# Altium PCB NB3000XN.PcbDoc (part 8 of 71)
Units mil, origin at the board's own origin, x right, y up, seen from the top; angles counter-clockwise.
Board outline 9527.56 x 6929.77 mil, 6 copper layers (Top Layer, GND+SHIELD, MidLayer1, MidLayer2, P2 - 3V3+5V0, Bottom Layer), stack 62.375 mil thick; 832 components, 1027 nets, 4655 pads, 4981 vias.
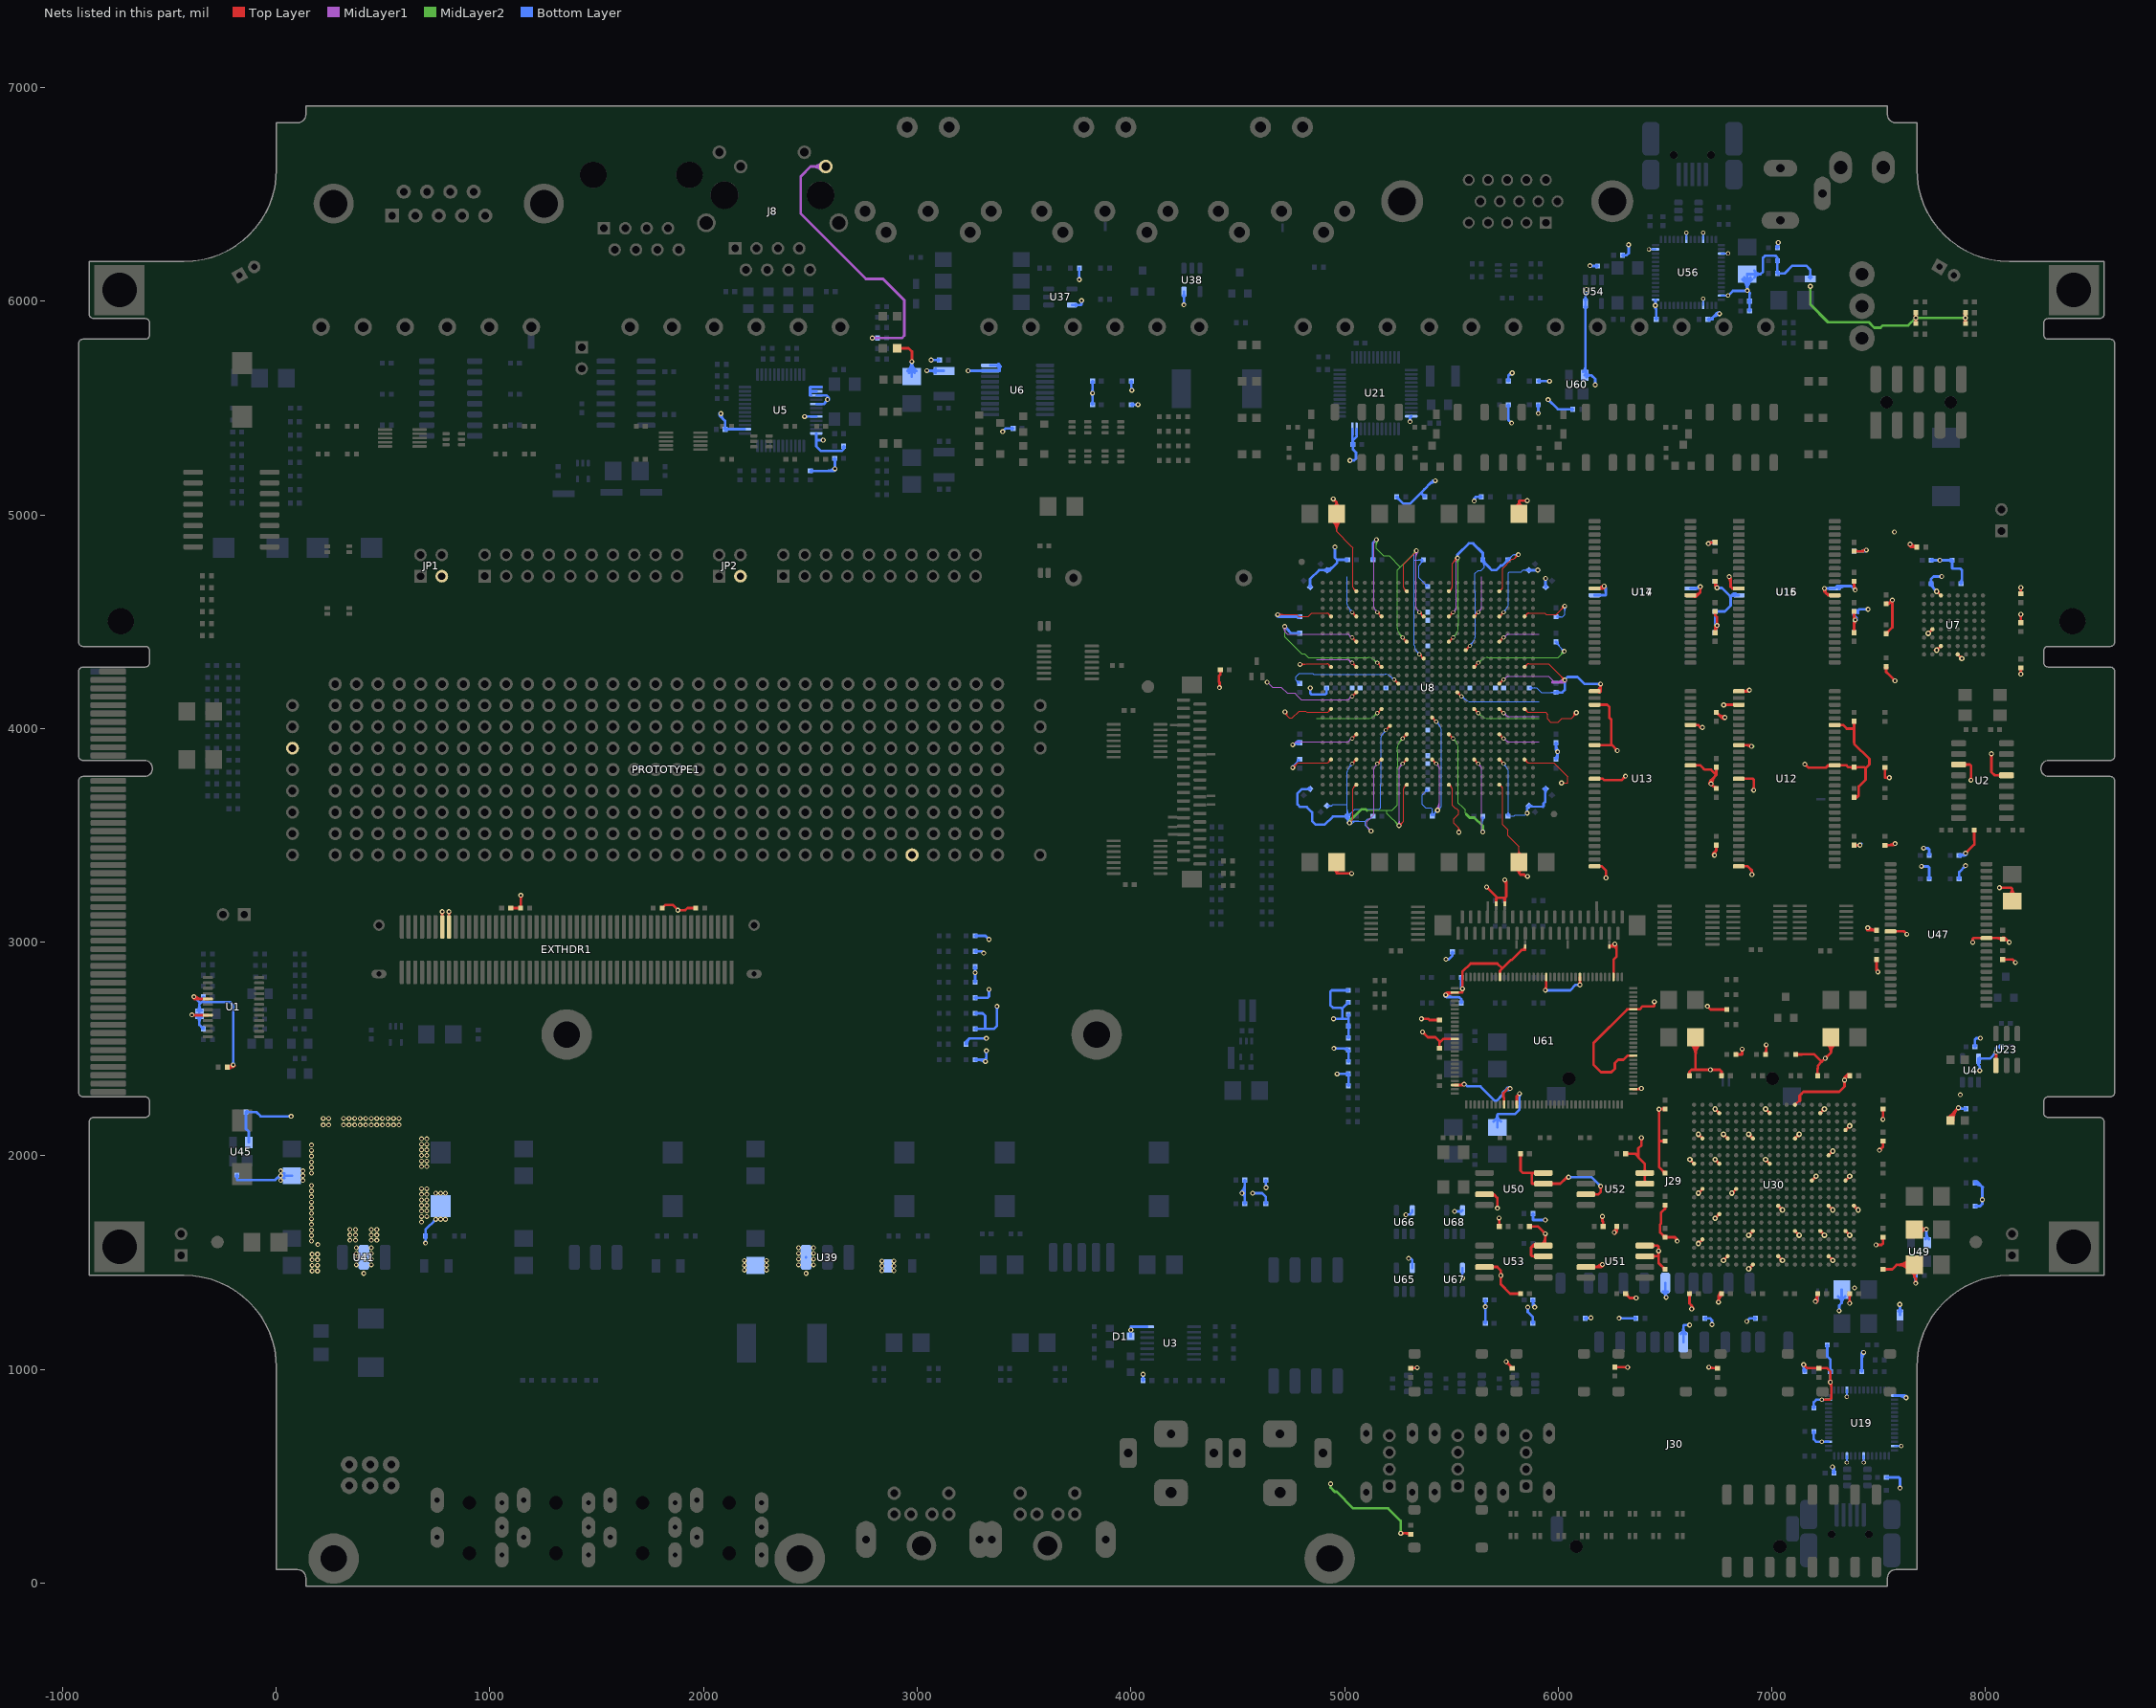
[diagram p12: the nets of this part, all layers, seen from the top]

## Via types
v1: diameter 23, hole 11.81, Top Layer to Bottom Layer, 3672 vias
v2: diameter 26, hole 11.81, Top Layer to Bottom Layer, 461 vias
v3: diameter 19, hole 11.81, Top Layer to Bottom Layer, tented both sides, 396 vias
v4: diameter 23.62, hole 11.81, Top Layer to Bottom Layer, 288 vias
v5: diameter 20, hole 11.81, Top Layer to Bottom Layer, 91 vias
v6: diameter 23, hole 11.81, Top Layer to Bottom Layer, tented both sides, 50 vias
v7: diameter 31, hole 11.81, Top Layer to Bottom Layer, 15 vias
v8: diameter 27.56, hole 11.81, Top Layer to Bottom Layer, tented both sides, 4 vias
v9: diameter 29, hole 11.81, Top Layer to Bottom Layer, 3 vias
v10: diameter 21, hole 11.81, Top Layer to Bottom Layer, 1 vias

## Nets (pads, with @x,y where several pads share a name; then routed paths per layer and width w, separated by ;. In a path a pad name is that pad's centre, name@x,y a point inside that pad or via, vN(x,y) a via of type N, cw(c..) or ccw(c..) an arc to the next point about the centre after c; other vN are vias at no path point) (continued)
3V3: (continued)
  Bottom Layer w4: v1@4757.52,3824.04 4758.52,3825.04 4758.7,3825.04 C322.1@4790,3856.34 ; v1@4757.52,3826.21 ccw(c4757.52,3831.87) 4761.53,3827.87 ; v1(4757.52,3924.04) v1@4758.52,3925.04 ; v1@4759.02,3816.71 cw(c4779.92,3816.71) 4765.14,3831.48 ; v1@4763.02,3816.71 cw(c4793.58,3816.71) 4771.97,3838.31 ; v1@4767.02,3816.71 cw(c4807.23,3816.71) C322.1@4778.8,3845.14 ; C322.1@4780.19,3856.34 cw(c4756.5,3856.34) 4773.25,3839.59 cw(c4790,3822.84) C322.1@4790,3846.53 ; C335.1@4780.19,4210.78 ccw(c4757.43,4211.05) 4773.53,4227.14 ; C323.1@4781.46,3928.28 ccw(c4773.19,3923.61) 4773.19,3933.11 ; C323.1@4781.46,3937.93 cw(c4773.19,3942.6) 4773.19,3933.11 ; C322.1@4784.19,3856.34 cw(c4770.16,3856.34) 4780.08,3846.42 cw(c4790,3836.5) C322.1@4790,3850.53 ; C335.1@4784.19,4210.74 ccw(c4770.71,4210.9) 4780.24,4220.43 ccw(c4789.77,4229.96) C335.1@4789.93,4216.48 ; C335.1@4789.89,4220.48 cw(c4789.62,4243.24) 4773.53,4227.14 ; C323.1@4790,3933.11 4773.19,3933.11 ; C335.1@4790,4210.67 4773.52,4227.15 ; C326.1@4917.56,3638.82 4940.19,3638.82 ; C326.1@4921.8,3634.85 cw(c4930.96,3626.27) 4930.96,3638.82 cw(c4930.96,3651.37) C326.1@4921.8,3642.79 ; C326.1@4924.72,3632.11 cw(c4940.19,3617.62) 4940.19,3638.82 ; C326.1@4924.72,3645.53 ccw(c4940.19,3660.01) 4940.19,3638.82 ; 4940.19,3639.04 4945.86,3644.71 5005,3644.71 ; 4948.52,3591.71 5000.42,3591.71 ; C331.1@5008.06,3596.94 ccw(c4998.8,3606.2) 5011.9,3606.2 ; 5008.57,3644.71 5005,3644.71 ; 5011.61,3644.71 5005,3644.71 ; C331.1@5011.9,3596.9 5011.9,3660 5011.9,3670 5011.9,3679.78 5011.9,3738.04 5011.9,3796.3 cw(c5035.67,3796.3) 5018.86,3813.11 5025.28,3820.84 ; 5011.9,3601.86 ccw(c5026.86,3601.86) C331.1@5016.28,3591.28 ; 5011.9,3611.51 ccw(c5036.51,3611.51) C331.1@5019.11,3594.11 ; 5011.9,3621.17 ccw(c5046.17,3621.17) C331.1@5021.94,3596.94 ; 5011.9,3648.22 5011.9,3655.26 ; 5011.9,4710 5011.9,4641.96 5011.9,4583.7 ccw(c5035.67,4583.7) 5018.86,4566.89 5025.28,4559.16 ; C331.1@5012.8,3580.44 cw(c5009.71,3566.97) v1@5023.52,3566.97 ; C331.1@5013.7,3584.34 cw(c5010.86,3572) 5023.52,3572 ; C331.1@5014.59,3588.24 cw(c5012.02,3577.02) 5023.52,3577.02 ; C331.1@5015,3595.81 ccw(c5015,3609.84) 5024.92,3599.92 ccw(c5034.84,3590) C331.1@5020.81,3590 ; C331.1@5015,3599.81 ccw(c5015,3623.5) 5031.75,3606.75 ccw(c5048.5,3590) C331.1@5024.81,3590 ; v1@5016.81,3565.09 ccw(c5000.59,3581.31) 5023.52,3581.31 ccw(c5046.46,3581.31) v1@5030.24,3565.09 ; v1@5019.64,3562.26 ccw(c5010.25,3571.65) 5023.52,3571.65 ccw(c5036.8,3571.65) v1@5027.41,3562.26 ; v1@5021.76,3560.14 cw(c5037.61,3544.29) 5037.61,3566.71 ; v1@5024.58,3557.31 cw(c5047.26,3534.64) 5047.26,3566.71 ; v1@5027.41,3554.49 cw(c5056.92,3524.98) 5056.92,3566.71 ; v3@5028.28,3834.37 cw(c5010.45,3831.22) 5025.28,3820.84 ; v3@5028.28,4545.63 ccw(c5010.45,4548.78) 5025.28,4559.16 ; v1@5030.24,3551.66 cw(c5066.58,3515.32) 5066.58,3566.71 ; v3@5036.97,3828.28 ccw(c5040.12,3810.45) 5025.28,3820.84 ; v3@5036.97,4551.72 cw(c5040.12,4569.55) 5025.28,4559.16 ; v1@5115.02,3520.71 ccw(c5092.09,3520.71) 5108.31,3536.93 ccw(c5124.52,3553.14) v1@5124.52,3530.21 ; v1@5119.02,3520.71 ccw(c5105.75,3520.71) 5115.14,3530.1 ccw(c5124.52,3539.49) v1@5124.52,3526.21 ; v1(5124.52,3520.71) 5098.52,3546.71 5098.52,3566.71 ; C330.1@5133.11,3590 5119.82,3576.71 5108.52,3576.71 5098.52,3566.71 ; 5169.38,3655.26 5169.38,3660 ; v3@5185.76,3991.85 cw(c5167.93,3988.7) 5182.76,3978.32 ; v3@5194.45,3985.76 ccw(c5197.6,3967.93) 5182.76,3978.32 ; v3@5225.05,4228.72 ccw(c5207.01,4227.14) 5218.65,4241.01 ; v3@5231.87,4236.84 cw(c5230.29,4254.88) 5218.65,4241.01 ; v1(5336.67,4832.5) 5337.54,4833.37 5339.52,4833.37 5326.77,4820.62 5326.77,4790 ; v3@5343.16,4348.13 ccw(c5325.12,4349.71) 5338.99,4361.35 ; 5350.34,4765.34 ccw(c5328,4787.67) C332.1@5359.54,4789.45 ; v3@5351.28,4354.95 cw(c5352.86,4372.99) 5338.99,4361.35 ; 5356.65,4771.65 ccw(c5339.97,4788.34) C332.1@5363.53,4789.67 ; 5362.26,4777.26 cw(c5369.33,4770.19) C332.1@5369.33,4780.19 ; C332.1@5362.39,4783.06 ccw(c5345.65,4766.31) 5345.65,4790 ccw(c5345.65,4813.69) C332.1@5362.39,4796.94 ; 5362.97,4777.97 ccw(c5351.93,4789.02) C332.1@5367.52,4789.9 ; C332.1@5365.22,4785.89 ccw(c5355.3,4775.97) 5355.3,4790 ccw(c5355.3,4804.03) C332.1@5365.22,4794.11 ; C317.1@5380.19,3715.59 cw(c5356.5,3715.59) 5373.25,3698.84 cw(c5390,3682.09) C317.1@5390,3705.78 ; C315.1@5380.19,4664.41 ccw(c5356.5,4664.41) 5373.25,4681.16 ccw(c5390,4697.91) C315.1@5390,4674.22 ; C317.1@5384.19,3715.59 cw(c5370.16,3715.59) 5380.08,3705.67 cw(c5390,3695.75) C317.1@5390,3709.78 ; C315.1@5384.19,4664.41 ccw(c5370.16,4664.41) 5380.08,4674.33 ccw(c5390,4684.25) C315.1@5390,4670.22 ; C317.1@5390,3715.59 5365,3690.59 5365,3670 5365,3660 5365,3645 5380,3630 5405,3630 5410.67,3624.33 C333.1@5410.67,3590 5410.67,3593.19 v1(5435.52,3618.04) 5453.23,3635.75 5453.23,3651.25 5453.23,3655.26 5453.23,3660 5453.23,3670 5453.23,3876.1 5453.23,3895.52 5453.23,3969.64 5453.23,3989.14 ccw(c5411.5,3989.14) 5441.01,4018.65 ; C313.1@5390,3873.07 C313.1@5390,3882.3 ; C315.1@5390,4664.41 5347.5,4706.91 5347.5,4710 5347.5,4720 5347.5,4762.5 5369.33,4784.33 C332.1@5369.33,4790 5326.77,4790 ; C333.1@5403.73,3596.94 ccw(c5386.98,3613.69) 5410.67,3613.69 ccw(c5434.36,3613.69) C333.1@5417.61,3596.94 ; C333.1@5406.56,3594.11 ccw(c5396.64,3604.03) 5410.67,3604.03 ccw(c5424.7,3604.03) C333.1@5414.78,3594.11 ; C333.1@5410.67,3599.81 ccw(c5410.67,3615.8) 5421.98,3604.5 ; C333.1@5416.48,3590 cw(c5438.2,3590) 5422.84,3605.36 ; C333.1@5420.48,3590 cw(c5451.86,3590) v1@5429.67,3612.19 ; v1@5426.02,3618.04 cw(c5403.09,3618.04) 5419.31,3601.82 cw(c5435.52,3585.61) v1@5435.52,3608.54 ; v3@5428.72,4025.05 cw(c5427.14,4007.01) 5441.01,4018.65 ; v1@5430.02,3618.04 cw(c5416.75,3618.04) 5426.13,3608.65 cw(c5435.52,3599.26) v1@5435.52,3612.54 ; v1@5435.52,3623.54 ccw(c5435.52,3636.82) 5444.91,3627.43 ccw(c5454.3,3618.04) v1@5441.02,3618.04 ; v1@5435.52,3627.54 ccw(c5435.52,3650.48) 5451.74,3634.26 ccw(c5467.96,3618.04) v1@5445.02,3618.04 ; v3@5436.84,4031.87 ccw(c5454.88,4030.29) 5441.01,4018.65 ; v3@5548.13,4143.16 cw(c5549.71,4125.12) 5561.35,4138.99 ; v3@5554.95,4151.28 ccw(c5572.99,4152.86) 5561.35,4138.99 ; v3@5585.55,4394.24 ccw(c5582.4,4412.07) 5597.24,4401.68 ; v3@5594.24,4388.15 cw(c5612.07,4391.3) 5597.24,4401.68 ; 5595.52,4866.71 5646.89,4815.34 ; C328.1@5639.95,3583.06 cw(c5623.2,3566.31) 5646.89,3566.31 cw(c5670.57,3566.32) C328.1@5653.83,3583.06 ; v1@5640.47,3522.76 ccw(c5624.98,3538.25) 5646.89,3538.25 ; C291.1@5640.8,4782.31 cw(c5619.23,4755.04) 5654,4755.04 ; C328.1@5642.78,3585.89 cw(c5632.86,3575.97) 5646.89,3575.97 cw(c5660.92,3575.97) C328.1@5651,3585.89 ; C291.1@5643.29,4785.44 cw(c5625.77,4763.3) 5654,4763.3 ; v1@5643.3,3519.93 ccw(c5634.64,3528.59) 5646.89,3528.59 ; C291.1@5645.77,4788.58 cw(c5632.31,4771.57) 5654,4771.57 ; 5646.89,3530.04 ccw(c5661.19,3530.04) v1@5651.08,3519.93 ; 5646.89,3539.7 ccw(c5670.85,3539.7) v1@5653.91,3522.76 ; C328.1@5646.89,3590 5646.89,3516.34 v1(5647.19,3516.04) ; C291.1@5646.89,4790 5654,4782.89 5654,4777.9 5654,4755.77 5638.23,4740 5624.8,4740 5610.62,4725.82 5610.62,4720 5610.62,4710 ; C291.1@5648.25,4791.72 cw(c5638.85,4779.83) C291.1@5654,4779.83 ; v3@5743.03,3828.28 cw(c5739.88,3810.45) 5754.72,3820.84 ; v3@5743.03,4551.72 ccw(c5739.88,4569.55) 5754.72,4559.16 ; v3@5751.72,3834.37 ccw(c5769.55,3831.22) 5754.72,3820.84 ; v3@5751.72,4545.63 cw(c5769.55,4548.78) 5754.72,4559.16 ; C329.1@5758.06,3596.94 ccw(c5734.24,3620.76) 5767.93,3620.76 ; C329.1@5760.89,3594.11 ccw(c5743.89,3611.11) 5767.93,3611.11 ; C307.1@5765,4790 5789.38,4814.37 v1(5813.52,4814.37) ; C307.1@5765,4795.81 ccw(c5765,4809.84) 5774.92,4799.92 ccw(c5784.84,4790) C307.1@5770.81,4790 ; C307.1@5765,4799.81 ccw(c5765,4823.5) 5781.75,4806.75 ccw(c5798.5,4790) C307.1@5774.81,4790 ; 5767.93,3606.61 ccw(c5781.61,3606.61) C329.1@5771.94,3596.94 ; 5768,3633.37 5767.93,3633.31 5767.93,3592.93 C329.1@5765,3590 5794.39,3590 5799.39,3595 5845,3595 v4(5855,3605) ; 5768.1,3633.37 5768.1,3655.26 5768.1,3660 5768.1,3670 5768.1,3679.78 5768.1,3738.04 5768.1,3796.3 ccw(c5744.33,3796.3) 5761.14,3813.11 5754.72,3820.84 ; v1@5806.81,4807.66 ccw(c5790.59,4791.44) 5790.59,4814.37 ccw(c5790.59,4837.31) v1@5806.81,4821.09 ; v1@5809.64,4810.49 ccw(c5800.25,4801.1) 5800.25,4814.37 ccw(c5800.25,4827.65) v1@5809.64,4818.26 ; C293.1@5855.5,4734.24 ccw(c5838.76,4717.5) 5838.76,4741.18 ccw(c5838.76,4764.87) C293.1@5855.5,4748.12 ; C293.1@5858.33,4737.07 ccw(c5848.41,4727.15) 5848.41,4741.18 ccw(c5848.41,4755.21) C293.1@5858.33,4745.29 ; C293.1@5862.44,4741.18 5835.18,4741.18 5827,4733 5772,4733 5768.1,4729.1 5768.1,4720 5768.1,4710 5768.1,4641.96 5768.1,4583.7 cw(c5744.33,4583.7) 5761.14,4566.89 5754.72,4559.16 ; C316.1@5864.41,4190 5900,4190 5920.67,4169.33 C334.1@5990,4169.33 ; C316.1@5868.52,4185.89 cw(c5878.44,4175.97) 5878.44,4190 cw(c5878.44,4204.03) C316.1@5868.52,4194.11 ; C316.1@5871.35,4183.06 cw(c5888.1,4166.31) 5888.1,4190 cw(c5888.1,4213.69) C316.1@5871.35,4196.94 ; 5893.33,4741.18 v1@5893.52,4741.37 ; v1@5896.19,4741.37 v1@5893.52,4741.37 ; 5910,4126.77 5703.9,4126.77 5684.48,4126.77 5610.36,4126.77 5590.86,4126.77 cw(c5590.86,4168.5) 5561.35,4138.99 ; v1@5910.86,4741.71 v1(5905,4741.71) 5896.52,4741.71 5893.86,4741.71 v1@5893.52,4741.37 ; C334.1@5983.06,4162.39 ccw(c5966.31,4145.65) 5966.31,4169.33 ccw(c5966.31,4193.02) C334.1@5983.06,4176.27 ; C334.1@5985.89,4165.22 ccw(c5975.97,4155.3) 5975.97,4169.33 ccw(c5975.97,4183.36) C334.1@5985.89,4173.44 ; C319.1@5990,4395.74 cw(c5990,4384.9) 5997.67,4392.56 ; C319.1@5990,4405.55 5990,4400.23 v1(6028.52,4361.71) ; C303.1@5990,4523.66 6020.14,4523.66 6030.52,4534.04 v1(6030.52,4573.71) ; C319.1@5991.81,4405.55 ccw(c6009.02,4405.55) 5996.85,4393.38 ; C303.1@5994.11,4519.55 cw(c6004.03,4509.63) 6004.03,4523.66 cw(c6004.03,4537.69) C303.1@5994.11,4527.77 ; C319.1@5995.81,4405.55 ccw(c6022.68,4405.55) 6003.68,4386.55 ; C303.1@5996.94,4516.72 cw(c6013.68,4499.98) 6013.68,4523.66 cw(c6013.69,4547.35) C303.1@5996.94,4530.6 ; C319.1@5999.81,4405.55 ccw(c6036.34,4405.55) 6010.51,4379.72 ; v1@6019.02,4361.71 ccw(c5996.09,4361.71) 6012.31,4377.93 ccw(c6028.52,4394.14) v1@6028.52,4371.21 ; v1@6023.02,4361.71 ccw(c6009.75,4361.71) 6019.14,4371.1 ccw(c6028.52,4380.49) v1@6028.52,4367.21 ; v1@6023.81,4566.99 cw(c6007.59,4550.77) 6030.52,4550.77 cw(c6053.46,4550.77) v1@6037.24,4566.99 ; v1@6026.64,4569.82 cw(c6017.25,4560.43) 6030.52,4560.43 cw(c6043.8,4560.43) v1@6034.41,4569.82 ; v1(6215.19,4666.71) 6223.52,4658.37 ; 4773.52,4227.15 4773.52,4243.71 4788.19,4258.37 4850,4258.37 4855.14,4253.23 4860,4253.23 4870,4253.23 5076.1,4253.23 5095.52,4253.23 5169.64,4253.23 5189.14,4253.23 cw(c5189.14,4211.5) 5218.65,4241.01 ; 5098.52,3566.71 5031.86,3566.71 v1(5023.52,3558.37) 5023.52,3568.61 5023.52,3581.48 C331.1@5015,3590 5048,3623 5163,3623 5169.38,3629.38 5169.38,3660 ; 5169.38,3660 5169.38,3670 5169.38,3679.78 5169.38,3738.04 5169.38,3953.78 cw(c5193.15,3953.78) 5176.34,3970.59 5182.76,3978.32 ; 5326.77,4790 5326.77,4724.74 5326.77,4720 5326.77,4710 5326.77,4503.9 5326.77,4484.48 5326.77,4410.36 5326.77,4390.86 ccw(c5368.5,4390.86) 5338.99,4361.35 ; 5597.24,4401.68 5603.66,4409.41 ccw(c5586.85,4426.22) 5610.62,4426.22 5610.62,4641.96 5610.62,4695 ; 5610.62,4695 5610.62,4700.22 5610.62,4710 ; 5610.62,4695 5610.62,4710
  Bottom Layer w8: C324.1@5866.26,3635 5926.9,3635 5928.52,3633.37 ; C324.1@5867.96,3644.34 ccw(c5890.52,3666.9) 5890.52,3635 ; v5(6424.34,6243.27) U56.55@6455.67,6243.27 ; v5@6428.58,6239.03 cw(c6438.82,6228.78) 6438.82,6243.27 cw(c6438.82,6257.75) v5@6428.58,6247.51 ; v5@6595.91,6316.42 cw(c6585.67,6306.18) 6600.16,6306.18 cw(c6614.64,6306.18) v5@6604.4,6316.42 ; U56.7@6600.16,6289.33 v5(6600.16,6320.66) ; v5@6674.65,6007.76 cw(c6664.41,5997.52) 6678.9,5997.52 cw(c6693.38,5997.52) v5@6683.14,6007.76 ; v5@6674.66,6316.42 cw(c6664.41,6306.18) 6678.9,6306.18 cw(c6693.38,6306.18) v5@6683.14,6316.42 ; U56.32@6678.9,5980.67 v5(6678.9,6012) ; U56.11@6678.9,6289.33 v5(6678.9,6320.66) ; U56.27@6764.33,6026.73 v5(6795.66,6026.73) ; U56.17@6764.33,6223.58 v5(6795.66,6223.58) ; v5@6791.42,6022.49 ccw(c6781.18,6012.25) 6781.18,6026.73 ccw(c6781.18,6041.22) v5@6791.42,6030.97 ; v5@6791.42,6219.34 ccw(c6781.18,6209.1) 6781.18,6223.58 ccw(c6781.18,6238.07) v5@6791.42,6227.83 ; v5(7234.34,858.27) U19.27@7265.67,858.27 ; v5@7238.58,854.03 cw(c7248.82,843.78) 7248.82,858.27 cw(c7248.82,872.75) v5@7238.58,862.51 ; v5@7346.86,568.58 ccw(c7336.62,578.82) 7351.1,578.82 ccw(c7365.59,578.82) v5@7355.34,568.58 ; v5@7346.86,877.24 ccw(c7336.62,887.48) 7351.1,887.48 ccw(c7365.59,887.48) v5@7355.35,877.24 ; v5(7351.1,564.34) U19.11@7351.1,595.67 ; v5(7351.1,873) U19.32@7351.1,904.33 ; v5@7425.6,568.58 ccw(c7415.36,578.82) 7429.84,578.82 ccw(c7444.33,578.82) v5@7434.09,568.58 ; v5(7429.84,564.34) U19.7@7429.84,595.67 ; U19.55@7574.33,641.73 v5(7605.66,641.73) ; v5@7601.42,637.49 ccw(c7591.18,627.25) 7591.18,641.73 ccw(c7591.18,656.22) v5@7601.42,645.97
  Bottom Layer w10: v1(5552.4,1427.4) U67.5@5552.4,1475.12
  Bottom Layer w11.81: v4@6450.82,5984.18 ccw(c6439.13,5995.87) 6455.67,5995.87 ; C174.2@6455.15,5919.18 ccw(c6445.07,5929.26) 6459.33,5929.26 ccw(c6473.59,5929.26) C174.2@6463.51,5919.18 ; 6455.67,5992.64 ccw(c6467.64,5992.64) v4@6459.18,5984.18 ; U56.43@6455.67,6007.05 6455.67,5982.85 6455.86,5982.85 6455.86,5980 6455.86,5966.04 ; 6455.86,5966.71 6455.86,5966.04 ; 6456.86,5964.85 6456.86,5965.04 6455.86,5966.04 ; C174.2@6459.33,5915 6459.33,5962.51 ; U19.43@7574.33,877.95 7618.28,877.95 v1(7628.52,867.71) ; U19.43@7590.28,877.95 cw(c7590.28,829.47) v1@7624.57,863.75 ; 7618.8,877.95 cw(c7618.8,857.98) v1@7632.92,872.1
